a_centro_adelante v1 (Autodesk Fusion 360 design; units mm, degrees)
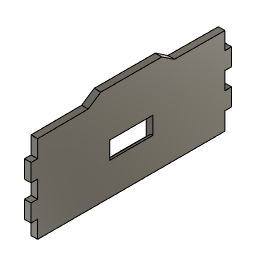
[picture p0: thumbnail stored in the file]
sketch "Sketch1" plane through (0, 0, 0) normal (1, 0, 0) x axis (0, 1, 0)
  line L1 (300, 220) -> (160, 220)
  line L2 (15, 0) -> (444.8, 0)
  line L3 (300, 220) -> (230, 220)
  line L4 (160, 220) -> (230, 220)
  line L5 (328.7889, 200.8074) -> (300, 220)
  line L6 (131.2111, 200.8074) -> (160, 220)
  line L7 (15.2, 160.15) -> (15.2, 200)
  line L8 (0, 160.15) -> (15.2, 160.15)
  line L9 (0, 119.6381) -> (15.2, 119.6381)
  line L10 (15.2, 79.7881) -> (0, 79.7881)
  line L11 (15.2, 119.6381) -> (15.2, 79.7881)
  line L12 (444.8, 160.15) -> (460, 160.15)
  line L13 (460, 120.3) -> (444.8, 120.3)
  line L14 (460, 160.15) -> (460, 120.3)
  line L15 (444.8, 160.15) -> (444.8, 200)
  line L16 (460, 160.15) -> (444.8, 160.15)
  line L17 (444.8, 120.3) -> (460, 120.3)
  line L18 (444.8, 80.45) -> (444.8, 120.3)
  line L19 (460, 80.45) -> (444.8, 80.45)
  line L20 (444.8, 200) -> (328.7889, 200.8074)
  line L21 (460, 120.3) -> (460, 160.15)
  line L22 (460, 40.6) -> (460, 80.45)
  line L23 (15.2, 160.15) -> (15.2, 200)
  line L24 (0, 160.15) -> (15.2, 160.15)
  line L25 (0, 79.7881) -> (0, 39.894)
  line L26 (0, 160.15) -> (0, 119.6381)
  line L27 (15, 39.894) -> (0, 39.894)
  line L28 (15, 0) -> (15, 39.894)
  line L29 (0, 0) -> (15, 0)
  line L30 (444.8, 80.45) -> (460, 80.45)
  line L31 (460, 40.6) -> (444.8, 40.6)
  line L32 (460, 80.45) -> (460, 40.6)
  line L33 (460, 40.6) -> (444.8, 40.6)
  line L34 (444.8, 40.6) -> (444.8, 0)
  line L35 (131.2111, 200.8074) -> (15.2, 200)
  line L36 (279.5, 64.4277) -> (180.5, 124.4277)
  line L37 (180.5, 64.4277) -> (279.5, 124.4277)
  line L38 (279.5, 114.5277) -> (180.5, 114.5277)
  line L39 (279.5, 74.3277) -> (279.5, 114.5277)
  line L40 (180.5, 74.3277) -> (279.5, 74.3277)
  line L41 (180.5, 114.5277) -> (180.5, 74.3277)
  line L42 (279.5, 74.3277) -> (180.5, 114.5277)
  line L43 (180.5, 74.3277) -> (279.5, 114.5277)
  point P2 (230, 220)
  point P38 (230, 94.4277)
  point P43 (230, 94.4277)
  point P3 (300, 220)
  point P4 (160, 220)
  point P5 (328.7889, 200.8074)
  point P6 (131.2111, 200.8074)
  point P10 (15.2, 119.6381)
  point P13 (15.2, 79.7881)
  point P14 (460, 160.15)
  point P15 (444.8, 160.15)
  point P17 (460, 120.3)
  point P22 (460, 80.45)
  point P29 (444.8, 80.45)
  point P31 (460, 40.6)
  point P40 (279.5, 114.5277)
  point P41 (279.5, 74.3277)
  horizontal L1
  horizontal L2
  vertical L25
  vertical L7
  horizontal L8
  horizontal L9
  horizontal L10
  vertical L11
  horizontal L12
  horizontal L13
  vertical L14
  vertical L15
  horizontal L16
  horizontal L17
  vertical L18
  horizontal L19
  coincident L1 P2
  collinear L21 L22
  vertical L23
  horizontal L24
  collinear L25 L26
  horizontal L27
  vertical L28
  horizontal L29
  horizontal L30
  horizontal L31
  vertical L32
  horizontal L33
  vertical L34
  coincident L36 P38
  coincident L37 P38
  horizontal L38
  perpendicular L38 L39
  parallel L38 L40
  parallel L39 L41
  coincident L42 P43
  coincident L43 P43
  coincident P38 P43
  dimension "d2" distance P2 P3 = 70
  dimension "d3" distance P2 P4 = 70
  dimension "d5" distance P3 P5 = 34.6
  dimension "d6" distance P4 P6 = 34.6
  dimension "d10" distance P10 P13 = 39.85
  dimension "d11" distance P14 P15 = 15.2
  dimension "d14" distance P17 P22 = 39.85
  dimension "d15" distance P22 P29 = 15.2
  dimension "d16" distance P22 P31 = 39.85
  dimension "d22" distance P40 P41 = 40.2
extrude "Extrude1" new body sketch "Sketch1" profile of L1 L22 L2 L26 L3 L4 L5 L6 L7 L8 L9 L10 L11 L12 L13 L14 L15 L16 L17 L18 L19 L20 L23 L24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 along normal blind 15
extrude "Extrude2" cut sketch "Sketch1" profile of L38 L39 L40 L41 along normal blind 20
sketch "Sketch2" plane through (0, 0, 0) normal (1, 0, 0) x axis (0, 1, 0)
  line L1 (180.5, 125) -> (279.5, 125)
  line L2 (279.5, 65) -> (180.5, 65)
  line L3 (279.5, 125) -> (279.5, 65)
  line L4 (180.5, 65) -> (279.5, 125)
  line L5 (279.5, 65) -> (180.5, 125)
  line L6 (180.5, 65) -> (180.5, 125)
  point P6 (230, 95)
  point P4 (180.5, 65)
  point P5 (279.5, 65)
  point P3 (180.5, 125)
  horizontal L1
  parallel L1 L2
  coincident L4 P6
  coincident L5 P6
  perpendicular L1 L6
  dimension "d25" distance P4 P5 = 99
  dimension "d26" distance P3 P4 = 60
extrude "Extrude3" cut sketch "Sketch2" profile of L1 L2 L3 L6 along normal blind 10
